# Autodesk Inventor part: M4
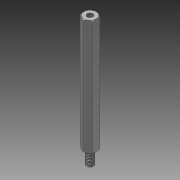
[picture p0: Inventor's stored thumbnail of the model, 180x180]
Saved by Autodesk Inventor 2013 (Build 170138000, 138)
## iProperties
Created: 2012-08
Part Number: M4
Material: Stahl
Document SubType Name: Modeling
Designer: rYan
Density: 7.85 g/cm^3
Author: rYan
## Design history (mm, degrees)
derived "Abstandsbolzen Typ B.ipt"
feature "Volumenkörper1::Abstandsbolzen Typ B.ipt"
tag "Bezeichnung1"
node "Volumenkörper1"
other parameters: "SW" = 7, "L" = 65, "d2" = 0, "l_" = 9, "d9" = 118 deg, "GA_" = 4, "A_" = 8, "d13" = 0, "d17" = 0.25, "d20" = 45 deg
